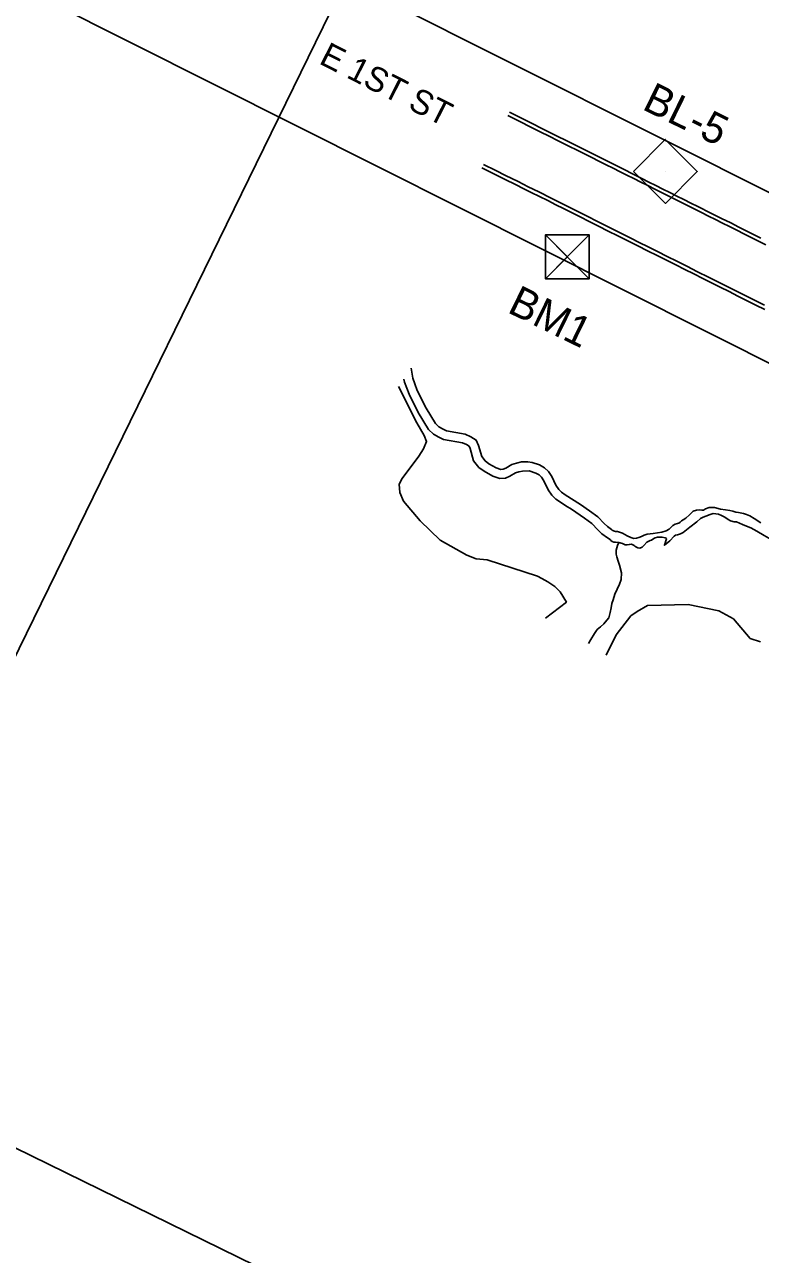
# Model space of a CAD drawing. Extents: x 1517485 to 1521905, y 636528 to 640355.
# Drawn here: x 1519215 to 1519698, y 637862 to 638669 of the extents above; entities that cross this region are included whole.
import ezdxf

# ---------------------------------------------------------------- set-up
doc = ezdxf.new("R2010")
doc.units = 0
for name, color, linetype in [('CTL Secondary Horizontal and Vertical CELL', 7, 'Continuous'), ('CTL Secondary Horizontal and Vertical Text', 7, 'Continuous'), ('CTL Vertical Benchmark CELL', 7, 'Continuous'), ('CTL Vertical Benchmark Text', 7, 'Continuous'), ('Exist Hydro Stream or Body of Water', 7, 'Continuous'), ('Exist Right of Way Line', 7, 'Continuous'), ('Exist Roads Curbs', 7, 'Continuous'), ('Exist Roads EOP', 7, 'Continuous'), ('Exist Roads EOP Text', 7, 'Continuous'), ('Exist Vegetation Woods Line', 7, 'Continuous'), ('Scratch_Level_3', 7, 'Continuous')]:
    doc.layers.add(name, color=color, linetype=linetype)

msp = doc.modelspace()

# ---------------------------------------------------------------- linework, layer by layer
at = {"layer": 'CTL Secondary Horizontal and Vertical CELL'}
msp.add_line((1519635.21, 638572.39), (1519635.21, 638572.39), dxfattribs=at)
msp.add_lwpolyline([(1519614.35, 638572.46), (1519635.31, 638593.42), (1519656.31, 638572.42), (1519635.35, 638551.46)], close=True, dxfattribs=at)
at = {"layer": 'CTL Vertical Benchmark CELL'}
msp.add_line((1519570.99, 638516.37), (1519570.99, 638516.37), dxfattribs=at)
msp.add_lwpolyline([(1519556.59, 638530.72), (1519585.34, 638530.72), (1519585.34, 638501.97), (1519556.59, 638501.97)], close=True, dxfattribs=at)
for points in [[(1519585.34, 638530.72), (1519556.59, 638501.97), (1519570.97, 638516.34), (1519585.34, 638501.97), (1519556.59, 638530.72)], [(1519570.97, 638516.34), (1519585.34, 638530.72), (1519556.59, 638530.72), (1519570.97, 638516.34)], [(1519570.97, 638516.34), (1519556.59, 638501.97), (1519585.34, 638501.97), (1519570.97, 638516.34)]]:
    msp.add_lwpolyline(points, dxfattribs=at)
at = {"layer": 'Exist Hydro Stream or Body of Water'}
for p, q in [((1519463.59, 638436.2), (1519464.17, 638434.23)), ((1519468.38, 638443.31), (1519469.63, 638436.69)), ((1519469.63, 638436.69), (1519470.88, 638433.03)), ((1519540.97, 638381.88), (1519537.57, 638381)), ((1519544.99, 638381.96), (1519540.97, 638381.88)), ((1519544.99, 638381.96), (1519547.81, 638381.4)), ((1519546.02, 638375.85), (1519541.51, 638375.78)), ((1519579.72, 638353.84), (1519569.61, 638360.27)), ((1519597.33, 638339.33), (1519599.94, 638337.36))]:
    msp.add_line(p, q, dxfattribs=at)
for points in [[(1519464.17, 638434.23), (1519467.11, 638426.27), (1519473.15, 638414.16), (1519479.77, 638403.12), (1519483.23, 638400.03), (1519486.71, 638398.03), (1519489.76, 638396.54), (1519502.23, 638394.38), (1519504.91, 638393.17), (1519506.46, 638392.15), (1519507.17, 638390.51), (1519509.42, 638382.59), (1519512.8, 638378.25), (1519516.3, 638375.64), (1519522.04, 638372.42), (1519526.61, 638370.99), (1519530.32, 638371.16), (1519533.33, 638372.48), (1519536.92, 638374.63), (1519539.1, 638375.32), (1519541.51, 638375.78)], [(1519470.88, 638433.03), (1519472.51, 638428.61), (1519478.31, 638416.99), (1519484.35, 638406.91), (1519486.69, 638404.82), (1519489.47, 638403.23), (1519491.59, 638402.19), (1519503.97, 638400.05), (1519507.75, 638398.34), (1519511.17, 638396.1), (1519512.72, 638392.49), (1519514.76, 638385.3), (1519516.95, 638382.48), (1519519.51, 638380.58), (1519524.38, 638377.85), (1519527.37, 638376.91), (1519528.96, 638376.99), (1519530.63, 638377.72), (1519534.48, 638380.02), (1519537.57, 638381)], [(1519569.61, 638360.27), (1519567.14, 638361.9), (1519565.41, 638363.68), (1519563.39, 638366.53), (1519560.76, 638372.22), (1519558.52, 638375.6), (1519555.97, 638377.99), (1519552.77, 638379.81), (1519547.81, 638381.4)], [(1519570.05, 638353.02), (1519567.19, 638354.87), (1519563.39, 638357.38), (1519560.91, 638359.94), (1519558.32, 638363.59), (1519555.64, 638369.36), (1519554.03, 638371.81), (1519552.48, 638373.25), (1519550.4, 638374.44), (1519546.02, 638375.85)], [(1519597.36, 638332.04), (1519593.68, 638334.64), (1519591.03, 638337.26), (1519587.02, 638341.34), (1519582.16, 638344.99), (1519573.72, 638350.79), (1519570.05, 638353.02)], [(1519597.33, 638339.33), (1519595.21, 638341.43), (1519590.93, 638345.8), (1519585.61, 638349.79), (1519579.72, 638353.84)], [(1519638.94, 638338.78), (1519640.2, 638340), (1519641.85, 638340.98), (1519643.28, 638341.29), (1519644.26, 638341.66), (1519645.1, 638342.37), (1519645.95, 638343.24), (1519647.01, 638343.83), (1519648.75, 638344.83), (1519651.12, 638347.16), (1519653.69, 638349.58), (1519655.76, 638350.21), (1519657.58, 638350.28), (1519659.22, 638350.2), (1519660.43, 638350.2), (1519661.58, 638350.91), (1519664.08, 638351.91), (1519667.63, 638351.89), (1519671.46, 638350.76), (1519674.79, 638350.32), (1519677.59, 638349.91), (1519679.68, 638349.42), (1519681.5, 638348.93), (1519683.3, 638348.71), (1519686.69, 638347.9), (1519688.57, 638347.32), (1519690.79, 638346.37), (1519693.66, 638344.61)], [(1519670.27, 638347.5), (1519666.7, 638348.04), (1519664.67, 638347.34), (1519662, 638346.27), (1519660.1, 638345.53), (1519658.45, 638344.61), (1519656.05, 638342.48), (1519651.33, 638339.06), (1519647.04, 638335.42), (1519645.28, 638334.53), (1519643.26, 638334), (1519641.97, 638333.79)], [(1519670.27, 638347.5), (1519672.14, 638346.75), (1519674.41, 638345.47), (1519676.52, 638343.96), (1519678.15, 638343.05), (1519680.41, 638342.55), (1519681.98, 638342.52), (1519684.02, 638341.72), (1519686.02, 638340.7), (1519688.56, 638339.74), (1519691.38, 638338.46)], [(1519693.66, 638344.61), (1519697.98, 638341.88)], [(1519607.14, 638328.17), (1519604.87, 638329), (1519602.56, 638329.06), (1519601.53, 638329.07), (1519600.47, 638329.65), (1519599.62, 638330.28), (1519599.02, 638330.94), (1519597.36, 638332.04)], [(1519610.28, 638333.26), (1519607.14, 638335.01), (1519603.93, 638336.06), (1519602.58, 638336.17), (1519601.32, 638336.59), (1519600.47, 638337.06), (1519599.94, 638337.36)], [(1519607.14, 638328.17), (1519608.85, 638327.43), (1519610.17, 638327.38), (1519611.7, 638327.69), (1519613.08, 638327.81), (1519613.91, 638327.38), (1519614.42, 638327.1), (1519614.81, 638326.87), (1519615.28, 638326.44), (1519616.01, 638326), (1519617.2, 638325.34), (1519618.61, 638325.14), (1519620.03, 638325.88), (1519621.27, 638326.88), (1519623.17, 638329.1), (1519625.3, 638330.26), (1519626.24, 638330.4), (1519627.7, 638331.6), (1519628.67, 638331.9), (1519630.26, 638332.36), (1519633.2, 638332.45), (1519635.25, 638332.07), (1519635.93, 638331.69), (1519636, 638331.25), (1519634.76, 638327.09), (1519638.21, 638329.93), (1519641.06, 638332.98), (1519641.97, 638333.79)], [(1519610.28, 638333.26), (1519612.58, 638332.16), (1519614.69, 638331.6), (1519616.33, 638331.72), (1519617.95, 638332.14), (1519619.65, 638332.91), (1519621.37, 638333.8), (1519623.34, 638334.5), (1519627.31, 638334.81), (1519632.94, 638335.7), (1519635.94, 638336.63), (1519637.84, 638337.67), (1519638.94, 638338.78)], [(1519691.38, 638338.46), (1519695.48, 638336.35), (1519700.17, 638333.45), (1519703.16, 638331.81), (1519706.87, 638330.52), (1519709.3, 638328.88), (1519712.63, 638327.27), (1519715.76, 638326.15), (1519719.71, 638325.16), (1519724.49, 638324.19), (1519729.17, 638324.49), (1519734.14, 638324.09), (1519737.89, 638322.87), (1519741.54, 638321.69), (1519742.92, 638321.36), (1519743.42, 638321.08), (1519743.99, 638320.6), (1519744.46, 638319.29), (1519744.71, 638317.03)], [(1519584.97, 638262.64), (1519586.45, 638265.19), (1519588.74, 638269.27), (1519590.62, 638271.82), (1519592.85, 638273.66), (1519594.95, 638275.52), (1519596.91, 638277.88), (1519598.13, 638279.47), (1519598.4, 638280.35), (1519599.11, 638283.03), (1519599.76, 638286.05), (1519600.21, 638288.86), (1519600.97, 638291.23), (1519602.14, 638295.11), (1519605.31, 638301.65), (1519606.29, 638304.71), (1519606.48, 638308.92), (1519605.18, 638314.05), (1519604.27, 638316.68), (1519603.4, 638319.57), (1519603.13, 638321.2), (1519603.12, 638323.84), (1519603.95, 638326.86), (1519604.87, 638329)]]:
    msp.add_lwpolyline(points, dxfattribs=at)
at = {"layer": 'Exist Right of Way Line'}
for p, q in [((1519196.36, 638813.06), (1519977, 638421.24)), ((1519230.66, 638683.96), (1520000.91, 638297.35))]:
    msp.add_line(p, q, dxfattribs=at)
at = {"layer": 'Exist Roads Curbs'}
for points in [[(1519533.09, 638611.27), (1519541.78, 638606.87), (1519547.03, 638604.22), (1519555.09, 638600.2), (1519563.1, 638596.2), (1519571.57, 638591.97), (1519580.2, 638587.65), (1519588.95, 638583.27), (1519597.72, 638578.89), (1519606.51, 638574.48), (1519615.45, 638569.99), (1519619.97, 638567.71), (1519624.53, 638565.41), (1519629.09, 638563.12), (1519633.67, 638560.82), (1519638.27, 638558.52), (1519642.87, 638556.22), (1519647.49, 638553.93), (1519652.1, 638551.65), (1519656.73, 638549.36), (1519665.24, 638545.15), (1519672.25, 638541.65), (1519678.22, 638538.65), (1519683.61, 638535.94), (1519689.77, 638532.83), (1519698.04, 638528.64)], [(1519514.87, 638574.87), (1519521.09, 638571.75), (1519529.84, 638567.35), (1519537.44, 638563.54), (1519542.1, 638561.23), (1519547.31, 638558.64), (1519552.76, 638555.93), (1519558.12, 638553.26), (1519563.38, 638550.62), (1519568.55, 638548.03), (1519573.82, 638545.38), (1519579.39, 638542.57), (1519585.27, 638539.61), (1519591.46, 638536.49), (1519597.82, 638533.28), (1519604.23, 638530.07), (1519610.69, 638526.84), (1519617.2, 638523.59), (1519623.66, 638520.37), (1519629.98, 638517.22), (1519636.17, 638514.12), (1519642.21, 638511.09), (1519648.15, 638508.11), (1519654.03, 638505.16), (1519659.83, 638502.23), (1519665.57, 638499.34), (1519671.31, 638496.45), (1519677.11, 638493.53), (1519682.99, 638490.58), (1519688.93, 638487.59), (1519694.83, 638484.63), (1519700.59, 638481.75)]]:
    msp.add_lwpolyline(points, dxfattribs=at)
at = {"layer": 'Exist Roads EOP'}
for points in [[(1519531.98, 638609.09), (1519539.44, 638605.35), (1519547.57, 638601.28), (1519553.24, 638598.43), (1519559.05, 638595.51), (1519565.02, 638592.52), (1519571.18, 638589.43), (1519578.26, 638585.9), (1519587, 638581.55), (1519591.74, 638579.19), (1519596.42, 638576.85), (1519601.04, 638574.53), (1519605.6, 638572.25), (1519610.13, 638569.97), (1519614.67, 638567.69), (1519619.22, 638565.41), (1519623.79, 638563.13), (1519628.33, 638560.86), (1519637.2, 638556.43), (1519645.86, 638552.1), (1519654.66, 638547.68), (1519659.13, 638545.44), (1519663.65, 638543.17), (1519668.21, 638540.88), (1519672.83, 638538.57), (1519677.49, 638536.25), (1519682.2, 638533.91), (1519686.95, 638531.54), (1519691.74, 638529.14), (1519696.56, 638526.71), (1519701.38, 638524.28)], [(1519700.38, 638484.6), (1519692.87, 638488.34), (1519685.56, 638492), (1519678.44, 638495.58), (1519671.17, 638499.24), (1519663.75, 638502.99), (1519656.47, 638506.65), (1519649.42, 638510.18), (1519642.79, 638513.5), (1519636.54, 638516.63), (1519630.26, 638519.78), (1519623.96, 638522.95), (1519618.07, 638525.89), (1519612.59, 638528.61), (1519607.04, 638531.4), (1519601.36, 638534.3), (1519595.58, 638537.22), (1519589.82, 638540.11), (1519584.83, 638542.62), (1519576.62, 638546.75), (1519568.63, 638550.79), (1519560.32, 638554.98), (1519552.29, 638558.97), (1519545.35, 638562.37), (1519538.61, 638565.73), (1519530.49, 638569.78), (1519524.15, 638572.96), (1519515.96, 638577.06)]]:
    msp.add_lwpolyline(points, dxfattribs=at)
at = {"layer": 'Exist Vegetation Woods Line'}
for points in [[(1519460.2, 638431.35), (1519472.2, 638407.44), (1519476.99, 638399.12), (1519478.6, 638395.13), (1519476.47, 638390.38), (1519473.46, 638385.6), (1519462.54, 638370.84), (1519460.5, 638367.15), (1519460.94, 638361.83), (1519463.42, 638355.97), (1519474.36, 638343.05), (1519487.47, 638330.53), (1519505.08, 638320.58), (1519511.16, 638318.24), (1519518.29, 638317.44), (1519551.44, 638306.85), (1519554.17, 638305.32), (1519558.13, 638303.11), (1519562.69, 638299.99), (1519566.35, 638296.45), (1519570.36, 638289.77), (1519556.56, 638279.17)], [(1519596.43, 638254.88), (1519602.94, 638268.3), (1519612.58, 638280.78), (1519616.75, 638283.64), (1519623.57, 638287.56), (1519650.28, 638288.25), (1519670.39, 638284.18), (1519680.06, 638278.77), (1519691.01, 638265.99), (1519697.76, 638263.82)]]:
    msp.add_lwpolyline(points, dxfattribs=at)
at = {"layer": 'Scratch_Level_3'}
for p, q in [((1519835.03, 639535.13), (1519081.21, 637993.84)), ((1519081.21, 637993.84), (1520017.02, 637536.16))]:
    msp.add_line(p, q, dxfattribs=at)

# ---------------------------------------------------------------- texts
at = {"layer": 'CTL Secondary Horizontal and Vertical Text'}
msp.add_text('BL-5', height=20, rotation=333.93772, dxfattribs=at).set_placement((1519619.39, 638613.52))
at = {"layer": 'CTL Vertical Benchmark Text'}
msp.add_text('BM1', height=20, rotation=333.93772, dxfattribs=at).set_placement((1519530.92, 638480.31))
at = {"layer": 'Exist Roads EOP Text'}
msp.add_text('E 1ST ST', height=16, rotation=333.12162, dxfattribs=at).set_placement((1519407.3, 638643.51))

doc.saveas('drawing.dxf')
